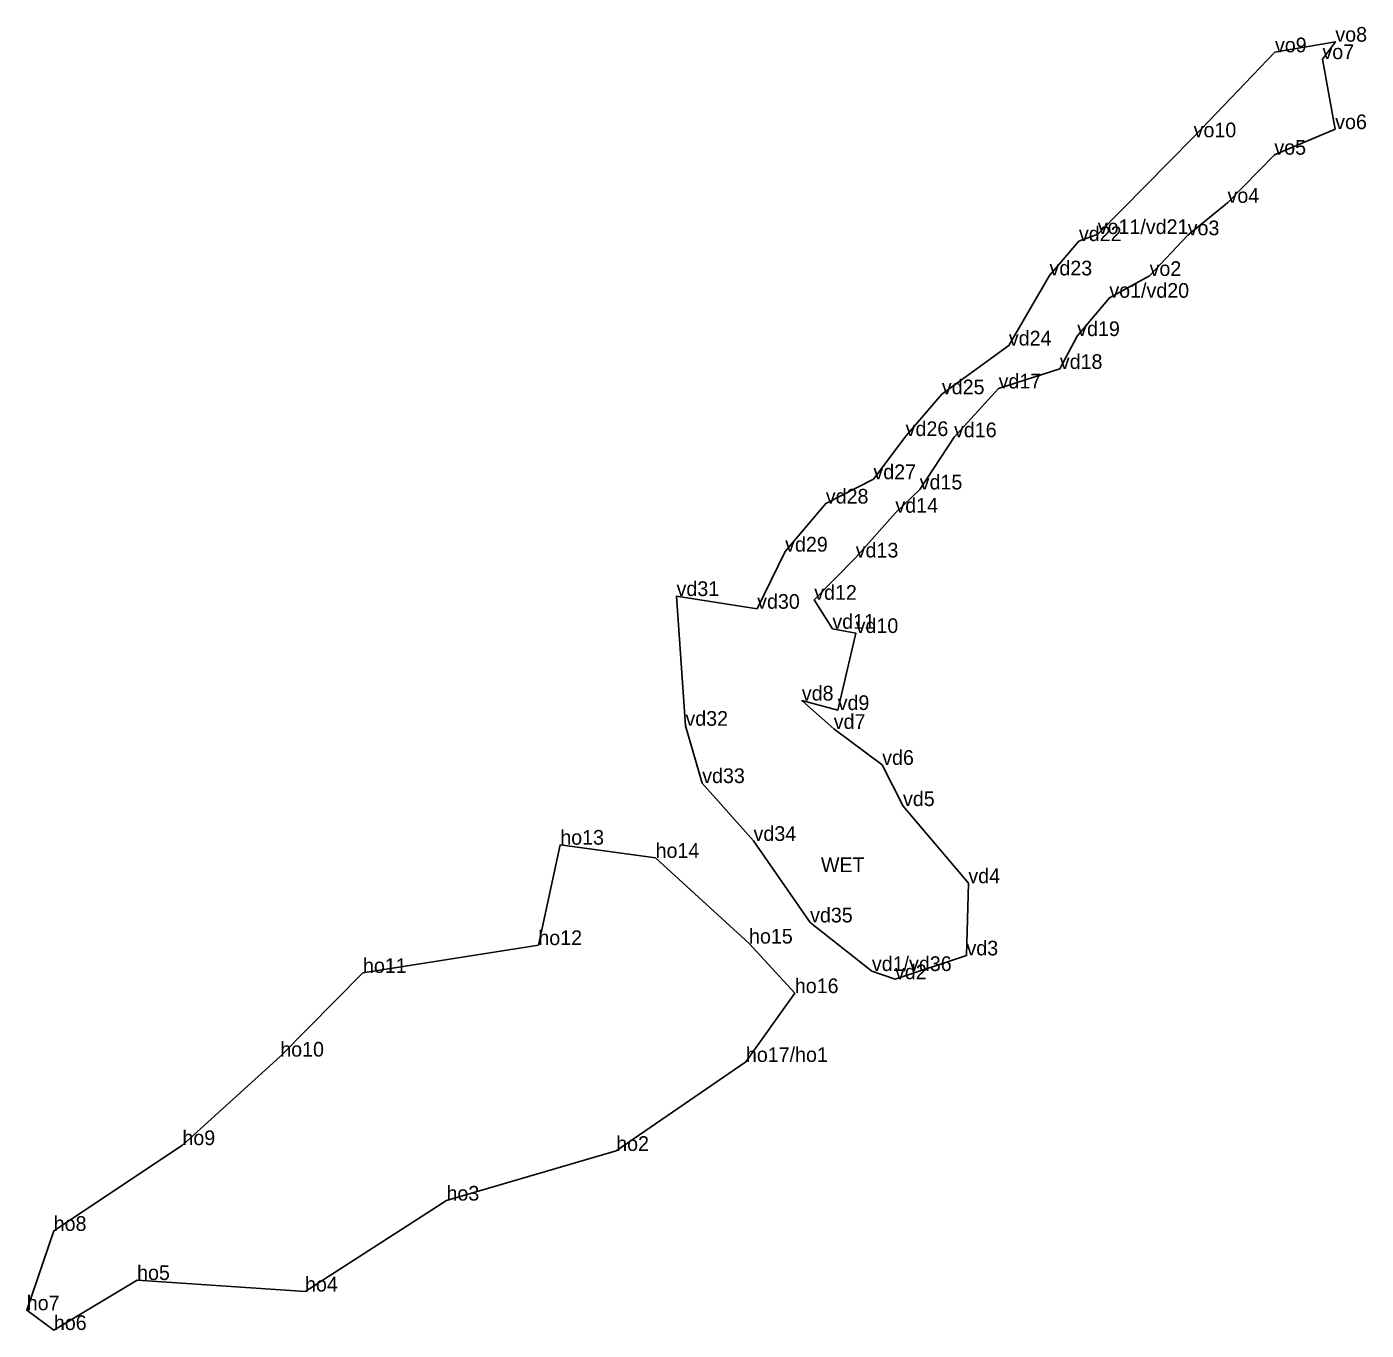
# Model space of a CAD drawing. Extents: x 2072529 to 2267990, y 436423 to 470008.
# Drawn here: x 2167162.1 to 2167618, y 442816.9 to 443260.7 of the extents above; entities that cross this region are included whole.
import ezdxf

# ---------------------------------------------------------------- set-up
doc = ezdxf.new("R2010")
doc.units = 0
doc.layers.add('Level 3', color=7, linetype='Continuous')
doc.layers.add('Old_Level_52', color=7, linetype='Continuous')

msp = doc.modelspace()

# ---------------------------------------------------------------- linework, layer by layer
at = {"layer": 'Level 3'}
for p, q in [((2167586.962, 443252.018), (2167586.962, 443252.018)), ((2167607.525, 443255.633), (2167607.525, 443255.633)), ((2167603.12, 443249.683), (2167603.12, 443249.683)), ((2167607.461, 443225.851), (2167607.461, 443225.851)), ((2167559.284, 443223.085), (2167559.284, 443223.085)), ((2167586.761, 443217.156), (2167586.761, 443217.156)), ((2167570.805, 443200.769), (2167570.805, 443200.769)), ((2167526.65, 443190.143), (2167526.65, 443190.143)), ((2167557.258, 443189.734), (2167557.258, 443189.734)), ((2167520.234, 443187.739), (2167520.234, 443187.739)), ((2167510.238, 443176.061), (2167510.238, 443176.061)), ((2167544.283, 443175.885), (2167544.283, 443175.885)), ((2167530.589, 443168.448), (2167530.589, 443168.448)), ((2167496.385, 443152.189), (2167496.385, 443152.189)), ((2167519.656, 443155.405), (2167519.656, 443155.405)), ((2167513.737, 443144.225), (2167513.737, 443144.225)), ((2167473.595, 443135.582), (2167473.595, 443135.582)), ((2167492.903, 443137.557), (2167492.903, 443137.557)), ((2167461.265, 443121.363), (2167461.265, 443121.363)), ((2167477.72, 443120.969), (2167477.72, 443120.969)), ((2167450.286, 443106.678), (2167450.286, 443106.678)), ((2167466.05, 443103.176), (2167466.05, 443103.176)), ((2167434.09, 443098.373), (2167434.09, 443098.373)), ((2167457.766, 443095.265), (2167457.766, 443095.265)), ((2167420.242, 443082.007), (2167420.242, 443082.007)), ((2167444.264, 443080.01), (2167444.264, 443080.01)), ((2167383.281, 443066.894), (2167383.281, 443066.894)), ((2167430.134, 443065.604), (2167430.134, 443065.604)), ((2167410.714, 443062.55), (2167410.714, 443062.55)), ((2167436.313, 443055.742), (2167436.313, 443055.742)), ((2167444.242, 443054.3), (2167444.242, 443054.3)), ((2167425.926, 443031.313), (2167425.926, 443031.313)), ((2167438.127, 443028.077), (2167438.127, 443028.077)), ((2167386.298, 443022.717), (2167386.298, 443022.717)), ((2167436.789, 443021.654), (2167436.789, 443021.654)), ((2167453.269, 443009.417), (2167453.269, 443009.417)), ((2167392.016, 443003.213), (2167392.016, 443003.213)), ((2167460.359, 442995.386), (2167460.359, 442995.386)), ((2167409.496, 442983.515), (2167409.496, 442983.515)), ((2167343.708, 442982.233), (2167343.708, 442982.233)), ((2167376.143, 442977.75), (2167376.143, 442977.75)), ((2167482.602, 442969.126), (2167482.602, 442969.126)), ((2167428.733, 442955.769), (2167428.733, 442955.769)), ((2167336.237, 442948.055), (2167336.237, 442948.055)), ((2167407.949, 442948.575), (2167407.949, 442948.575)), ((2167481.959, 442944.54), (2167481.959, 442944.54)), ((2167276.551, 442938.569), (2167276.551, 442938.569)), ((2167449.772, 442939.22), (2167449.772, 442939.22)), ((2167457.635, 442936.432), (2167457.635, 442936.432)), ((2167423.533, 442931.687), (2167423.533, 442931.687)), ((2167248.39, 442910.073), (2167248.39, 442910.073)), ((2167406.886, 442908.264), (2167406.886, 442908.264)), ((2167215.097, 442879.951), (2167215.097, 442879.951)), ((2167362.733, 442877.977), (2167362.733, 442877.977)), ((2167304.969, 442861.055), (2167304.969, 442861.055)), ((2167171.276, 442850.759), (2167171.276, 442850.759)), ((2167199.666, 442834.014), (2167199.666, 442834.014)), ((2167256.825, 442830.102), (2167256.825, 442830.102)), ((2167162.116, 442823.708), (2167162.116, 442823.708)), ((2167171.331, 442816.992), (2167171.331, 442816.992))]:
    msp.add_line(p, q, dxfattribs=at)
at = {"layer": 'Old_Level_52'}
for points in [[(2167449.772, 442939.22), (2167457.635, 442936.432), (2167481.959, 442944.54), (2167482.602, 442969.126), (2167460.359, 442995.386), (2167453.269, 443009.417), (2167436.789, 443021.654), (2167425.926, 443031.313), (2167438.127, 443028.077), (2167444.242, 443054.3), (2167436.313, 443055.742), (2167430.134, 443065.604), (2167444.264, 443080.01), (2167457.766, 443095.265), (2167466.05, 443103.176), (2167477.72, 443120.969), (2167492.903, 443137.557), (2167513.737, 443144.225), (2167519.656, 443155.405), (2167530.589, 443168.448), (2167544.283, 443175.885), (2167557.258, 443189.734), (2167570.805, 443200.769), (2167586.761, 443217.156), (2167607.461, 443225.851), (2167603.12, 443249.683), (2167607.525, 443255.633), (2167586.962, 443252.018), (2167559.284, 443223.085), (2167526.65, 443190.143), (2167520.234, 443187.739), (2167510.238, 443176.061), (2167496.385, 443152.189), (2167473.595, 443135.582), (2167461.265, 443121.363), (2167450.286, 443106.678), (2167434.09, 443098.373), (2167420.242, 443082.007), (2167410.714, 443062.55), (2167383.281, 443066.894), (2167386.298, 443022.717), (2167392.016, 443003.213), (2167409.496, 442983.515), (2167428.733, 442955.769)], [(2167406.886, 442908.264), (2167362.733, 442877.977), (2167304.969, 442861.055), (2167256.825, 442830.102), (2167199.666, 442834.014), (2167171.331, 442816.992), (2167162.116, 442823.708), (2167171.276, 442850.759), (2167215.097, 442879.951), (2167248.39, 442910.073), (2167276.551, 442938.569), (2167336.237, 442948.055), (2167343.708, 442982.233), (2167376.143, 442977.75), (2167407.949, 442948.575), (2167423.533, 442931.687)]]:
    msp.add_lwpolyline(points, close=True, dxfattribs=at)

# ---------------------------------------------------------------- texts
for s, p in [('vo9', (2167586.962, 443252.018)), ('vo8', (2167607.525, 443255.633)), ('vo7', (2167603.12, 443249.683)), ('vo6', (2167607.461, 443225.851)), ('vo10', (2167559.284, 443223.085)), ('vo5', (2167586.761, 443217.156)), ('vo4', (2167570.805, 443200.769)), ('vd22', (2167520.234, 443187.739)), ('vo11/vd21', (2167526.65, 443190.143)), ('vo3', (2167557.258, 443189.734)), ('vd23', (2167510.238, 443176.061)), ('vo2', (2167544.283, 443175.885)), ('vo1/vd20', (2167530.589, 443168.448)), ('vd24', (2167496.385, 443152.189)), ('vd19', (2167519.656, 443155.405)), ('vd18', (2167513.737, 443144.225)), ('vd17', (2167492.903, 443137.557)), ('vd25', (2167473.595, 443135.582)), ('vd26', (2167461.265, 443121.363)), ('vd16', (2167477.72, 443120.969)), ('vd27', (2167450.286, 443106.678)), ('vd15', (2167466.05, 443103.176)), ('vd28', (2167434.09, 443098.373)), ('vd14', (2167457.766, 443095.265)), ('vd29', (2167420.242, 443082.007)), ('vd13', (2167444.264, 443080.01)), ('vd31', (2167383.281, 443066.894)), ('vd12', (2167430.134, 443065.604)), ('vd30', (2167410.714, 443062.55)), ('vd11', (2167436.313, 443055.742)), ('vd10', (2167444.242, 443054.3)), ('vd8', (2167425.926, 443031.313)), ('vd9', (2167438.127, 443028.077)), ('vd32', (2167386.298, 443022.717)), ('vd7', (2167436.789, 443021.654)), ('vd6', (2167453.269, 443009.417)), ('vd33', (2167392.016, 443003.213)), ('vd5', (2167460.359, 442995.386)), ('vd34', (2167409.496, 442983.515)), ('ho13', (2167343.708, 442982.233)), ('ho14', (2167376.143, 442977.75)), ('WET', (2167432.423, 442972.881)), ('vd4', (2167482.602, 442969.126)), ('vd35', (2167428.733, 442955.769)), ('ho12', (2167336.237, 442948.055)), ('ho15', (2167407.949, 442948.575)), ('vd3', (2167481.959, 442944.54)), ('ho11', (2167276.551, 442938.569)), ('vd1/vd36', (2167449.772, 442939.22)), ('vd2', (2167457.635, 442936.432)), ('ho16', (2167423.533, 442931.687)), ('ho10', (2167248.39, 442910.073)), ('ho17/ho1', (2167406.886, 442908.264)), ('ho9', (2167215.097, 442879.951)), ('ho2', (2167362.733, 442877.977)), ('ho3', (2167304.969, 442861.055)), ('ho8', (2167171.276, 442850.759)), ('ho5', (2167199.666, 442834.014)), ('ho4', (2167256.825, 442830.102)), ('ho7', (2167162.116, 442823.708)), ('ho6', (2167171.331, 442816.992))]:
    msp.add_text(s, height=5).set_placement(p)

doc.saveas('drawing.dxf')
